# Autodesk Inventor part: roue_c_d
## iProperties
Author: Philippe
Shininess: 21.0
Angle Display Precision: 2
Document Length Units: 11269
Document Angle Units: 11283
Document Time Units: 11279
Document Mass Units: 11290
Document Length Units Precision: 3
Document Angle Units Precision: 2
Compacted: False
PropertySet Name: _Private Model Information
Created: 2002-05
Part Number: roue_c_d
Material: Par défaut
Document SubType Name: Modélisation
Designer: Philippe
Control State: 0
Master: False
Checked Out: False
PropertySet Name: Design Tracking Control
Density: 1.0
Volumn: 3.4335507025963503
Area: 23.63813651773031
PropertySet Name: Model Information
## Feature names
1. Extrusion1
2. Extrusion2
3. Réseau circulaire1 [Circular Pattern]
4. Perçage1 [Hole]
